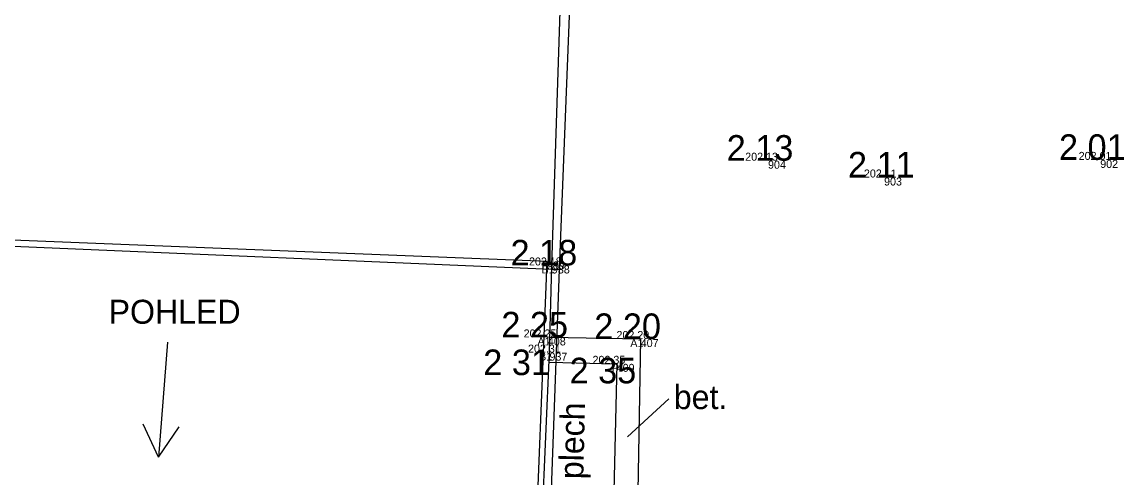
# Model space of a CAD drawing. Extents: x -599717 to -599336, y -1161826 to -1161587.
# Drawn here: x -599519.47 to -599505.7, y -1161673.17 to -1161667.47 of the extents above; entities that cross this region are included whole.
import ezdxf

# ---------------------------------------------------------------- set-up
doc = ezdxf.new("R2010")
doc.units = 0
for name, color, linetype in [('BODY', 7, 'Continuous'), ('BODY_CISLA', 7, 'Continuous'), ('BODY_KODY', 7, 'Continuous'), ('BODY_VYSKY_CELE', 7, 'Continuous'), ('G_BUDOVY', 7, 'Continuous'), ('G_POLOHOPIS', 7, 'Continuous'), ('G_REZ', 7, 'Continuous'), ('G_TEXTY', 7, 'Continuous'), ('H_KOTY_VYSKOVE', 7, 'Continuous'), ('KN_Hranice parcel', 7, 'Continuous'), ('KN_Vnitřní kresba', 7, 'Continuous')]:
    doc.layers.add(name, color=color, linetype=linetype)

msp = doc.modelspace()

# ---------------------------------------------------------------- linework, layer by layer
at = {"layer": 'BODY'}
for p, q in [((-599510.15, -1161669.2), (-599510.15, -1161669.2)), ((-599506, -1161669.19), (-599506, -1161669.19)), ((-599508.7, -1161669.41), (-599508.7, -1161669.41)), ((-599512.91, -1161670.46), (-599512.91, -1161670.46)), ((-599512.85, -1161670.51), (-599512.85, -1161670.51)), ((-599512.9, -1161671.41), (-599512.9, -1161671.41)), ((-599511.74, -1161671.43), (-599511.74, -1161671.43)), ((-599512.88, -1161671.6), (-599512.88, -1161671.6)), ((-599512.04, -1161671.74), (-599512.04, -1161671.74))]:
    msp.add_line(p, q, dxfattribs=at)
at = {"layer": 'G_BUDOVY'}
for points in [[(-599513.039, -1161673.697), (-599512.97, -1161673.7), (-599512.88, -1161671.6), (-599512.85, -1161670.51), (-599512.64, -1161664.02), (-599522.37, -1161663.63), (-599522.585, -1161670.074)], [(-599513.08, -1161674.72), (-599512.91, -1161670.46), (-599542.25, -1161669.29), (-599542.22, -1161668.41), (-599556.9, -1161667.78), (-599562.67, -1161667.54), (-599563.198, -1161681.088)]]:
    msp.add_lwpolyline(points, dxfattribs=at)
at = {"layer": 'G_POLOHOPIS'}
for points in [[(-599513.15, -1161693.9), (-599512.82, -1161693.42), (-599512.48, -1161692.78), (-599512.24, -1161685.62), (-599512, -1161677.9), (-599511.9, -1161675.13), (-599511.88, -1161674.5), (-599511.82, -1161673.83), (-599511.78, -1161673.81), (-599511.74, -1161671.43), (-599512.875, -1161671.41)], [(-599512.883, -1161671.721), (-599512.04, -1161671.74), (-599512.08, -1161673.51), (-599512.961, -1161673.49)]]:
    msp.add_lwpolyline(points, dxfattribs=at)
at = {"layer": 'G_REZ'}
for p, q in [((-599517.65, -1161671.471), (-599517.763, -1161672.908)), ((-599517.763, -1161672.908), (-599517.957, -1161672.493)), ((-599517.763, -1161672.908), (-599517.506, -1161672.528))]:
    msp.add_line(p, q, dxfattribs=at)
at = {"layer": 'G_TEXTY'}
msp.add_line((-599511.389, -1161672.179), (-599511.905, -1161672.653), dxfattribs=at)
at = {"layer": 'KN_Hranice parcel'}
msp.add_lwpolyline([(-599562.4, -1161659.34), (-599562.42, -1161659.71), (-599562.46, -1161667.78), (-599541.8, -1161668.65), (-599541.8, -1161669.33), (-599524.19, -1161670.12), (-599523.91, -1161663.71), (-599521.82, -1161663.85), (-599512.51, -1161664.21), (-599512.76, -1161670.56), (-599512.86, -1161673.31)], dxfattribs=at)
at = {"layer": 'KN_Vnitřní kresba'}
msp.add_line((-599522.11, -1161670.16), (-599512.76, -1161670.56), dxfattribs=at)

# ---------------------------------------------------------------- texts
at = {"layer": 'BODY_CISLA'}
for s, p in [('904', (-599510.15, -1161669.3)), ('902', (-599506, -1161669.29)), ('903', (-599508.7, -1161669.51)), ('939', (-599512.91, -1161670.56)), ('938', (-599512.85, -1161670.61)), ('408', (-599512.9, -1161671.51)), ('407', (-599511.74, -1161671.53)), ('937', (-599512.88, -1161671.7)), ('409', (-599512.04, -1161671.84))]:
    msp.add_text(s, height=0.1, dxfattribs=at).set_placement(p)
at = {"layer": 'BODY_KODY'}
for s, p in [('B1', (-599512.98, -1161670.61)), ('B', (-599512.975, -1161670.56)), ('A1', (-599513.03, -1161671.51)), ('A1', (-599511.87, -1161671.53)), ('B1', (-599513.01, -1161671.7)), ('P', (-599512.101, -1161671.84))]:
    msp.add_text(s, height=0.1, dxfattribs=at).set_placement(p)
at = {"layer": 'BODY_VYSKY_CELE'}
for s, p in [('202.13 ', (-599510.435, -1161669.2)), ('202.01 ', (-599506.269, -1161669.19)), ('202.11 ', (-599508.952, -1161669.41)), ('202.18 ', (-599513.136, -1161670.51)), ('202.25 ', (-599513.203, -1161671.41)), ('202.20 ', (-599512.043, -1161671.43)), ('202.31 ', (-599513.148, -1161671.6)), ('202.35 ', (-599512.342, -1161671.74))]:
    msp.add_text(s, height=0.1, dxfattribs=at).set_placement(p)
at = {"layer": 'G_REZ'}
msp.add_text('POHLED', height=0.3, dxfattribs=at).set_placement((-599518.388, -1161671.239))
at = {"layer": 'G_TEXTY'}
msp.add_text('bet.', height=0.3, dxfattribs=at).set_placement((-599511.327, -1161672.306))
msp.add_text('plech', height=0.3, rotation=88.7054, dxfattribs=at).set_placement((-599512.458, -1161673.185))
at = {"layer": 'H_KOTY_VYSKOVE'}
for s, p in [(' 2 13', (-599510.785, -1161669.2)), (' 2 01', (-599506.634, -1161669.19)), (' 2 11', (-599509.27, -1161669.41)), (' 2 18', (-599513.485, -1161670.51)), (' 2 25', (-599513.6, -1161671.41)), (' 2 20', (-599512.439, -1161671.43)), (' 2 31', (-599513.826, -1161671.881)), (' 2 35', (-599512.748, -1161671.984))]:
    msp.add_text(s, height=0.32, dxfattribs=at).set_placement(p)

doc.saveas('drawing.dxf')
